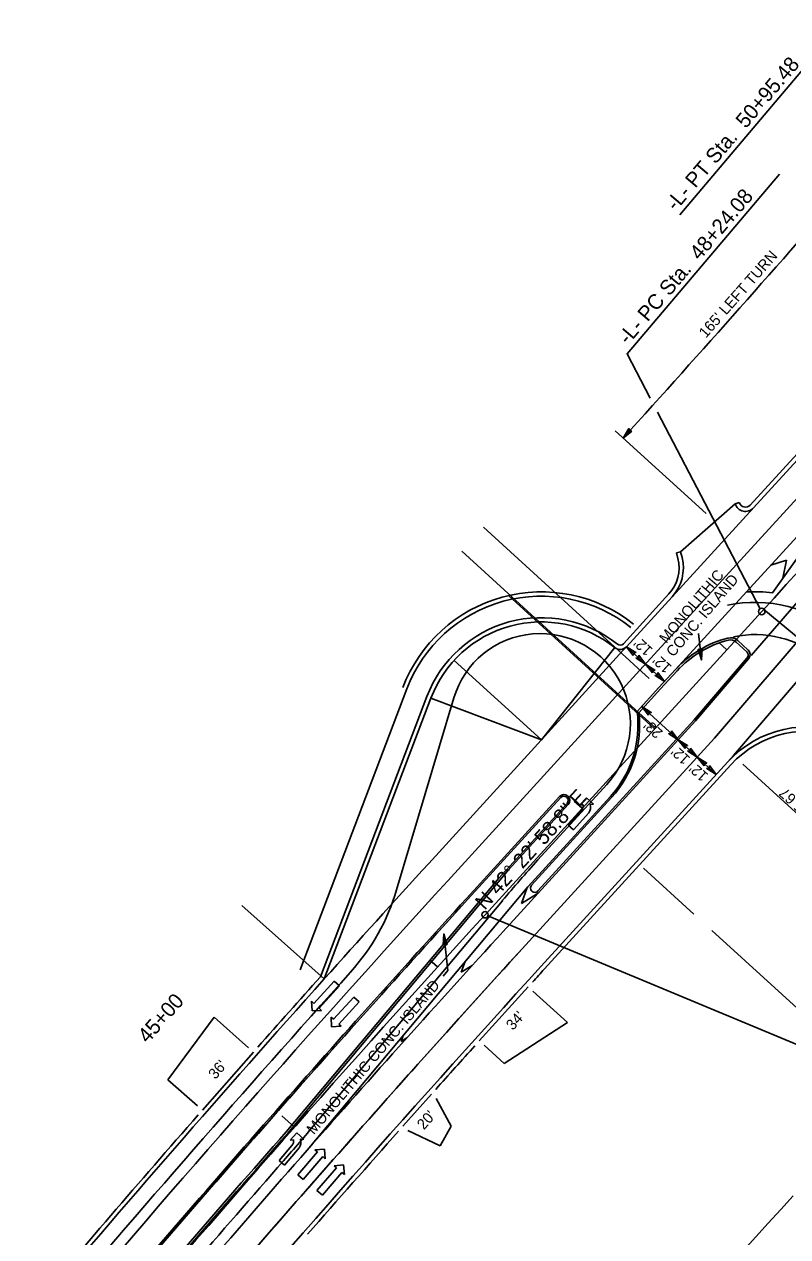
# Model space of a CAD drawing. Extents: x 1761082 to 1764358, y 421907 to 425434.
# Drawn here: x 1763432 to 1763787, y 424529 to 425094 of the extents above; entities that cross this region are included whole.
import ezdxf

# ---------------------------------------------------------------- set-up
doc = ezdxf.new("R2010")
doc.units = 0
for name, color, linetype in [('MARK DUAL LEFT TURN ARROWS CELL', 7, 'Continuous'), ('MARK HOOKS CENTER LEFT TURN ARROW CELL', 7, 'Continuous'), ('MARK HOOKS CENTER STRAIGHT LEFT TURN ARROW CELL', 7, 'Continuous'), ('MARK HOOKS STRAIGHT RIGHT TURN ARROW CELL', 7, 'Continuous'), ('MARK LEFT TURN ARROW CELL', 7, 'Continuous'), ('MARK ONLY WORD SYMBOL CELL', 7, 'Continuous'), ('MARK STRAIGHT RIGHT ARROW CELL', 7, 'Continuous'), ('MARK UTURN ARROW CELL', 7, 'Continuous'), ('Prop Conc Driveway', 7, 'Continuous'), ('Prop Horizontal Alignment Tick Large', 7, 'Continuous'), ('Prop Mkg 3ft Min Skp 3ft Wide White', 7, 'Continuous'), ('Prop Mkg Skp Wht', 7, 'Continuous'), ('Prop Mkg Solid White Diagonals', 7, 'Continuous'), ('Prop Mkg Solid White Edge Line', 7, 'Continuous'), ('Prop Mkg Solid White Lane Line', 7, 'Continuous'), ('Prop Mkg Solid White Multiple Diagonals V8i', 7, 'Continuous'), ('Prop Mkg Solid Yel Skip LT', 7, 'Continuous'), ('Prop Mkg Solid Yel Skip RT', 7, 'Continuous'), ('Prop Mkg Solid Yellow Diagonals', 7, 'Continuous'), ('Prop Mkg Solid Yellow Edge Line', 7, 'Continuous'), ('Prop Mkg Solid Yellow Lane Line', 7, 'Continuous'), ('Prop Mkr CR 80ft Spc', 7, 'Continuous'), ('Scratch_Level_0', 7, 'Continuous'), ('Scratch_Level_1', 7, 'Continuous'), ('Scratch_Level_5', 7, 'Continuous')]:
    doc.layers.add(name, color=color, linetype=linetype)

msp = doc.modelspace()

# ---------------------------------------------------------------- linework, layer by layer
at = {"layer": 'MARK DUAL LEFT TURN ARROWS CELL'}
for p, q in [((1763657.13, 424827.44), (1763725.22, 424765.29)), ((1763609.86, 424783.96), (1763560.14, 424653.11))]:
    msp.add_line(p, q, dxfattribs=at)
for radius in [69, 67]:
    msp.add_arc((1763672.49, 424760.17), radius, 51.5045, 159.1982, dxfattribs=at)
at = {"layer": 'MARK HOOKS CENTER STRAIGHT LEFT TURN ARROW CELL'}
for p, q in [((1763758.93, 424802.23), (1763755.24, 424805.6)), ((1763691.52, 424728.36), (1763687.83, 424731.73)), ((1763624.16, 424654.45), (1763620.46, 424657.8))]:
    msp.add_line(p, q, dxfattribs=at)
at = {"layer": 'MARK LEFT TURN ARROW CELL'}
for p, q in [((1763769.8, 424869.63), (1763835.19, 424941.15)), ((1763764.72, 424870.75), (1763762.82, 424870.15)), ((1763735.45, 424847.4), (1763737.39, 424847.88)), ((1763736.12, 424844.68), (1763735.45, 424847.4)), ((1763710.69, 424804.99), (1763731.93, 424828.22)), ((1763619.2, 424780.41), (1763569.62, 424649.9)), ((1763673.95, 424653.48), (1763760.81, 424748.66))]:
    msp.add_line(p, q, dxfattribs=at)
for centre, radius, start, end in [((1763767.58, 424871.66), 3, 197.5515, 317.5614), ((1763718.64, 424840.36), 18, 317.5614, 13.8599), ((1763672.49, 424760.17), 57, 51.5045, 159.1982), ((1763709.22, 424806.34), 2, 231.5008, 317.5614), ((1763796.27, 424716.3), 48, 67.2642, 137.617), ((1769289.17, 419529.14), 7601.94, 137.617012, 137.679215), ((1769289.17, 419529.14), 7676.94, 138.161609, 138.489892), ((1769289.17, 419529.14), 7601.94, 137.980695, 138.186669), ((1769289.17, 419529.14), 7676.94, 138.803366, 139.730103), ((1769289.17, 419529.14), 7601.94, 138.382631, 138.8659)]:
    msp.add_arc(centre, radius, start, end, dxfattribs=at)
at = {"layer": 'MARK ONLY WORD SYMBOL CELL'}
for p, q in [((1763666.38, 424645.15), (1763643.55, 424619.96)), ((1763514.61, 424587.77), (1763538.39, 424614.79)), ((1763621.29, 424595.16), (1763607.98, 424580.23))]:
    msp.add_line(p, q, dxfattribs=at)
at = {"layer": 'MARK STRAIGHT RIGHT ARROW CELL'}
msp.add_line((1763646.25, 424678.76), (1763775.16, 424820.01), dxfattribs=at)
for centre, start, end in [((1758132.25, 429969.63), 317.617012, 319.652488), ((1769289.17, 419529.14), 137.617012, 139.730103)]:
    msp.add_arc(centre, 7639.44, start, end, dxfattribs=at)
at = {"layer": 'MARK UTURN ARROW CELL'}
for points in [[(1763953.16, 425024.35), (1763812.18, 425093.6), (1763737.01, 425004.87)], [(1763723.17, 424919.43), (1763712.4, 424940.01), (1763783.41, 425023.83)], [(1763774.47, 424821.34), (1763726.57, 424912.93)], [(1763647.64, 424678.18), (1763914.92, 424566.85), (1763986.41, 424651.23)]]:
    msp.add_lwpolyline(points, dxfattribs=at)
for centre in [(1763775.16, 424820.01), (1763646.25, 424678.76)]:
    msp.add_circle(centre, 1.5, dxfattribs=at)
at = {"layer": 'Prop Conc Driveway'}
for p, q in [((1763684.72, 424628.48), (1763668.6, 424643.14)), ((1763498.47, 424601.92), (1763520.06, 424631)), ((1763520.06, 424631), (1763536.14, 424616.78)), ((1763655.12, 424609.51), (1763684.72, 424628.48)), ((1763645.78, 424617.94), (1763655.12, 424609.51)), ((1763512.36, 424589.75), (1763498.47, 424601.92)), ((1763623.53, 424593.16), (1763630.55, 424580.28)), ((1763610.22, 424578.23), (1763625.35, 424571.1)), ((1763625.35, 424571.1), (1763630.55, 424580.28))]:
    msp.add_line(p, q, dxfattribs=at)
at = {"layer": 'Prop Horizontal Alignment Tick Large'}
msp.add_line((1763557.56, 424579.85), (1763551.56, 424585.14), dxfattribs=at)
at = {"layer": 'Prop Mkg 3ft Min Skp 3ft Wide White'}
msp.add_line((1763646.25, 424678.76), (1763775.16, 424820.01), dxfattribs=at)
for centre, start, end in [((1758132.25, 429969.63), 317.617012, 319.652488), ((1769289.17, 419529.14), 137.617012, 139.730103)]:
    msp.add_arc(centre, 7639.44, start, end, dxfattribs=at)
at = {"layer": 'Prop Mkg Skp Wht'}
for p, q in [((1763771.27, 424868.28), (1763836.67, 424939.8)), ((1763737.39, 424847.88), (1763762.82, 424870.15)), ((1763738.06, 424845.16), (1763737.39, 424847.88)), ((1763712.17, 424803.64), (1763733.4, 424826.87)), ((1763621.07, 424779.7), (1763571.36, 424648.84)), ((1763672.48, 424654.83), (1763759.34, 424750.01))]:
    msp.add_line(p, q, dxfattribs=at)
for centre, radius, start, end in [((1763767.58, 424871.66), 5, 197.5515, 317.5614), ((1763718.64, 424840.36), 20, 317.5614, 13.8599), ((1763672.49, 424760.17), 55, 51.5008, 159.1982), ((1763709.22, 424806.34), 4, 231.5008, 317.5614), ((1763796.27, 424716.3), 50, 67.2642, 137.617), ((1769289.17, 419529.14), 7603.94, 137.617012, 139.730103), ((1769289.17, 419529.14), 7674.94, 138.158837, 139.730103)]:
    msp.add_arc(centre, radius, start, end, dxfattribs=at)
at = {"layer": 'Prop Mkg Solid White Diagonals'}
for p, q in [((1763768.27, 424801.25), (1763763.3, 424805.79)), ((1763743.72, 424769.61), (1763768.44, 424798.47)), ((1763735.7, 424792.33), (1763728.03, 424783.94)), ((1763728.03, 424783.94), (1763717.92, 424772.86)), ((1763670.92, 424689.84), (1763743.72, 424769.61)), ((1763681.5, 424733.33), (1763638.31, 424686)), ((1763652.63, 424695.76), (1763684.46, 424730.63)), ((1763705.19, 424733.33), (1763667.97, 424692.54)), ((1763553.57, 424577.59), (1763652.63, 424695.76))]:
    msp.add_line(p, q, dxfattribs=at)
for centre, radius, start, end in [((1763771.86, 424759.26), 49, 104.4881, 137.5628), ((1763760.6, 424802.83), 4, 47.617, 104.4881), ((1763766.92, 424799.77), 2, 319.4164, 47.617), ((1763668.26, 424767.03), 50, 317.617, 6.6974), ((1763682.98, 424731.98), 2, 317.617, 137.617), ((1763669.45, 424691.19), 2, 137.617, 317.617), ((1769289.17, 419529.14), 7650.19, 137.617012, 139.730103), ((1769289.17, 419529.14), 7640.94, 138.645864, 139.730103)]:
    msp.add_arc(centre, radius, start, end, dxfattribs=at)
at = {"layer": 'Prop Mkg Solid White Edge Line'}
for p, q in [((1763645.49, 424859.26), (1763722.71, 424788.79)), ((1763635.38, 424848.18), (1763717.92, 424772.86)), ((1763672.49, 424760.17), (1763631.86, 424797.24)), ((1763663.61, 424662.91), (1763753.14, 424761.02)), ((1763533.04, 424683.09), (1763571.37, 424648.86))]:
    msp.add_line(p, q, dxfattribs=at)
msp.add_arc((1769289.17, 419529.14), 7615.94, 137.617012, 139.730103, dxfattribs=at)
at = {"layer": 'Prop Mkg Solid White Lane Line'}
for p, q in [((1763768.27, 424801.25), (1763763.3, 424805.79)), ((1763743.72, 424769.61), (1763768.44, 424798.47)), ((1763728.03, 424783.94), (1763735.7, 424792.33)), ((1763717.92, 424772.86), (1763728.03, 424783.94)), ((1763670.92, 424689.84), (1763743.72, 424769.61)), ((1763638.31, 424686), (1763681.5, 424733.33)), ((1763652.63, 424695.76), (1763684.46, 424730.63)), ((1763667.97, 424692.54), (1763705.19, 424733.33)), ((1763652.63, 424695.76), (1763553.57, 424577.59))]:
    msp.add_line(p, q, dxfattribs=at)
for centre, radius, start, end in [((1763771.86, 424759.26), 49, 104.4881, 137.5628), ((1763760.6, 424802.83), 4, 47.617, 104.4881), ((1763766.92, 424799.77), 2, 319.4164, 47.617), ((1763668.26, 424767.03), 50, 317.617, 6.6974), ((1763682.98, 424731.98), 2, 317.617, 137.617), ((1763669.45, 424691.19), 2, 137.617, 317.617), ((1769289.17, 419529.14), 7650.19, 137.617012, 138.645864), ((1769289.17, 419529.14), 7650.19, 138.645864, 139.730103), ((1769289.17, 419529.14), 7640.94, 138.645864, 139.730103)]:
    msp.add_arc(centre, radius, start, end, dxfattribs=at)
at = {"layer": 'Prop Mkg Solid White Multiple Diagonals V8i'}
for p, q in [((1763734.96, 424793), (1763768.01, 424829.16)), ((1763672.49, 424760.17), (1763706.73, 424803.21)), ((1763672.49, 424760.17), (1763621.07, 424779.7))]:
    msp.add_line(p, q, dxfattribs=at)
for radius in [65, 50]:
    msp.add_arc((1763771.86, 424759.26), radius, 51.059, 101.278, dxfattribs=at)
at = {"layer": 'Prop Mkg Solid Yel Skip RT'}
for p, q in [((1763749.27, 424865.73), (1763706.88, 424904.25)), ((1763712.17, 424803.64), (1763729.9, 424787.46)), ((1763719.26, 424775.82), (1763753.98, 424744.14)), ((1763766.37, 424748.95), (1763797.92, 424720.16)), ((1763720.07, 424700.5), (1763743.52, 424679.1)), ((1763751.92, 424671.43), (1763823.83, 424605.81))]:
    msp.add_line(p, q, dxfattribs=at)
for points in [[(1763745.65, 424809.82), (1763747.08, 424797.45)], [(1763627.04, 424669.8), (1763629, 424652.81), (1763626.73, 424650.13)]]:
    msp.add_lwpolyline(points, dxfattribs=at)
for centre, radius, start, end in [((1758076.76, 430009.28), 7605.02, 317.799981, 319.027687), ((1769289.17, 419529.14), 7445.13, 137.617012, 139.730103)]:
    msp.add_arc(centre, radius, start, end, dxfattribs=at)
at = {"layer": 'Prop Mkg Solid Yellow Diagonals'}
for p, q in [((1763693.53, 424733.21), (1763690.49, 424729.89)), ((1763696.78, 424730.23), (1763693.53, 424733.21)), ((1763695.29, 424730.15), (1763696.78, 424730.23)), ((1763691.16, 424727.35), (1763685.05, 424720.53)), ((1763687.51, 424718.33), (1763694.55, 424726.18)), ((1763690.49, 424729.89), (1763691.97, 424729.97)), ((1763685.05, 424720.53), (1763687.51, 424718.33)), ((1763566.53, 424637.45), (1763575.97, 424647.79)), ((1763578.4, 424645.56), (1763568.96, 424635.22)), ((1763575.97, 424647.79), (1763578.4, 424645.56)), ((1763575.68, 424630.06), (1763585.11, 424640.4)), ((1763585.11, 424640.4), (1763587.55, 424638.18)), ((1763565.66, 424633.97), (1763565.42, 424638.46)), ((1763565.42, 424638.46), (1763566.53, 424637.45)), ((1763570.07, 424634.21), (1763565.66, 424633.97)), ((1763568.96, 424635.22), (1763570.07, 424634.21)), ((1763587.55, 424638.18), (1763578.11, 424627.84)), ((1763574.81, 424626.59), (1763574.57, 424631.07)), ((1763574.57, 424631.07), (1763575.68, 424630.06)), ((1763579.22, 424626.82), (1763574.81, 424626.59)), ((1763578.11, 424627.84), (1763579.22, 424626.82)), ((1763558.51, 424577.14), (1763555.55, 424573.76)), ((1763555.55, 424573.76), (1763557.03, 424573.87)), ((1763561.82, 424574.24), (1763558.51, 424577.14)), ((1763560.34, 424574.13), (1763561.82, 424574.24)), ((1763556.28, 424571.23), (1763550.32, 424564.28)), ((1763552.83, 424562.13), (1763559.69, 424570.14)), ((1763559.04, 424557.62), (1763568.16, 424568.24)), ((1763567.02, 424569.21), (1763571.43, 424569.58)), ((1763568.16, 424568.24), (1763567.02, 424569.21)), ((1763571.43, 424569.58), (1763571.8, 424565.11)), ((1763550.32, 424564.28), (1763552.83, 424562.13)), ((1763570.66, 424566.09), (1763561.54, 424555.47)), ((1763567.96, 424550.24), (1763577.09, 424560.86)), ((1763571.8, 424565.11), (1763570.66, 424566.09)), ((1763575.95, 424561.84), (1763580.35, 424562.2)), ((1763577.09, 424560.86), (1763575.95, 424561.84)), ((1763580.35, 424562.2), (1763580.73, 424557.73)), ((1763561.54, 424555.47), (1763559.04, 424557.62)), ((1763579.59, 424558.71), (1763570.47, 424548.09)), ((1763580.73, 424557.73), (1763579.59, 424558.71)), ((1763570.47, 424548.09), (1763567.96, 424550.24))]:
    msp.add_line(p, q, dxfattribs=at)
for centre, radius, start, end in [((1763688.74, 424729.53), 3.27, 318.1057, 7.7639), ((1763690.17, 424729.05), 5.25, 326.7817, 12.0934), ((1763553.81, 424573.35), 3.27, 319.4106, 9.0688), ((1763555.25, 424572.91), 5.25, 328.0867, 13.3984)]:
    msp.add_arc(centre, radius, start, end, dxfattribs=at)
at = {"layer": 'Prop Mkg Solid Yellow Edge Line'}
for p, q in [((1763718.44, 424792.72), (1763947.38, 425043.11)), ((1763753.14, 424761.02), (1763974.82, 425019.8)), ((1763733.4, 424826.87), (1763771.27, 424868.28)), ((1763762.01, 424752.93), (1763857.92, 424865.11)), ((1763770.31, 424799.5), (1763793, 424825.99)), ((1763620.03, 424702.69), (1763712.17, 424803.65)), ((1763628.89, 424694.6), (1763718.43, 424792.7)), ((1763663.61, 424662.91), (1763753.14, 424761.02)), ((1763759.34, 424750.01), (1763762.01, 424752.93))]:
    msp.add_line(p, q, dxfattribs=at)
for radius, start, end in [(7674.94, 137.617012, 138.158837), (7662.94, 137.617012, 139.730103), (7615.94, 137.617012, 138.644778), (7627.94, 138.644778, 139.730103), (7615.94, 138.644778, 139.730103)]:
    msp.add_arc((1769289.17, 419529.14), radius, start, end, dxfattribs=at)
at = {"layer": 'Prop Mkg Solid Yellow Lane Line'}
for points in [[(1763714.64, 424904.06), (1763710.59, 424900.83), (1763713.32, 424905.27), (1763713.56, 424904.18)], [(1763715.34, 424799.55), (1763712.17, 424803.64), (1763716.57, 424800.85), (1763715.48, 424800.62)], [(1763717.85, 424799.64), (1763721.03, 424795.55), (1763716.63, 424798.34), (1763717.72, 424798.57)], [(1763747.37, 424802.62), (1763747.08, 424797.45), (1763745.59, 424802.44), (1763746.57, 424801.9)], [(1763724.21, 424791.46), (1763721.03, 424795.55), (1763725.43, 424792.76), (1763724.34, 424792.53)], [(1763726.72, 424791.55), (1763729.9, 424787.46), (1763725.49, 424790.25), (1763726.59, 424790.48)], [(1763722.44, 424771.73), (1763719.26, 424775.82), (1763723.66, 424773.03), (1763722.57, 424772.8)], [(1763733.07, 424764.4), (1763736.25, 424760.31), (1763731.85, 424763.1), (1763732.94, 424763.33)], [(1763739.43, 424756.23), (1763736.25, 424760.31), (1763740.65, 424757.53), (1763739.56, 424757.3)], [(1763741.94, 424756.31), (1763745.12, 424752.23), (1763740.71, 424755.01), (1763741.81, 424755.25)], [(1763748.29, 424748.14), (1763745.12, 424752.23), (1763749.52, 424749.44), (1763748.42, 424749.21)], [(1763750.8, 424748.23), (1763753.98, 424744.14), (1763749.58, 424746.93), (1763750.67, 424747.16)], [(1763626.75, 424664.63), (1763627.04, 424669.8), (1763628.53, 424664.81), (1763627.55, 424665.35)]]:
    msp.add_lwpolyline(points, close=True, dxfattribs=at)
at = {"layer": 'Prop Mkr CR 80ft Spc'}
msp.add_line((1763776.07, 424821.01), (1763909.73, 424710.27), dxfattribs=at)
at = {"layer": 'Scratch_Level_0'}
for p, q in [((1763768.01, 424829.16), (1763823.69, 424890.05)), ((1763780.25, 424828.76), (1763823.69, 424890.05)), ((1763786.65, 424843.96), (1763779.36, 424841.56)), ((1763786.65, 424843.96), (1763785.06, 424835.53)), ((1763768.76, 424802.16), (1763763.97, 424806.52)), ((1763744.28, 424769.11), (1763769.01, 424797.99)), ((1763727.29, 424784.62), (1763734.96, 424793)), ((1763717.09, 424773.44), (1763727.29, 424784.62)), ((1763654.75, 424671), (1763744.28, 424769.11)), ((1763637.76, 424686.51), (1763680.95, 424733.83)), ((1763666.24, 424691.75), (1763704.64, 424733.83)), ((1763657.2, 424699.66), (1763685.01, 424730.13)), ((1763554.32, 424576.93), (1763657.2, 424699.66)), ((1763563.42, 424569.11), (1763666.24, 424691.75)), ((1763665.93, 424691.39), (1763663.19, 424684.06)), ((1763663.19, 424684.06), (1763670.99, 424688.81)), ((1763637.05, 424656.93), (1763635.2, 424651.99)), ((1763635.2, 424651.99), (1763640.22, 424655.04)), ((1763608.16, 424622.48), (1763607.13, 424619.71)), ((1763607.13, 424619.71), (1763609.84, 424621.35)), ((1763579.28, 424588.02), (1763578.93, 424587.09)), ((1763578.93, 424587.09), (1763579.73, 424587.57))]:
    msp.add_line(p, q, dxfattribs=at)
for centre, radius, start, end in [((1763771.86, 424759.26), 70, 83.1106, 93.1475), ((1763771.86, 424759.26), 50, 104.4881, 137.5628), ((1763760.6, 424802.83), 5, 47.617, 104.4881), ((1763766.74, 424799.94), 3, 319.4164, 47.617), ((1763668.26, 424767.03), 49.25, 317.617, 7.4761), ((1763682.98, 424731.98), 2.75, 317.617, 137.617), ((1769289.17, 419529.14), 7650.94, 137.617012, 138.645864), ((1769289.17, 419529.14), 7627.94, 137.617012, 138.644778), ((1769289.17, 419529.14), 7650.94, 138.645864, 139.730103), ((1769289.17, 419529.14), 7639.94, 138.645864, 139.730103)]:
    msp.add_arc(centre, radius, start, end, dxfattribs=at)
at = {"layer": 'Scratch_Level_1'}
for p, q in [((1763631.7, 424779.73), (1763605.07, 424690.32)), ((1763702.98, 424739.43), (1763670.89, 424704.27)), ((1763567.14, 424581.32), (1763654.32, 424685.31))]:
    msp.add_line(p, q, dxfattribs=at)
for centre in [(1763631.7, 424779.73), (1763631.7, 424779.73), (1763631.7, 424779.73), (1763631.7, 424779.73), (1763631.7, 424779.73), (1763631.7, 424779.73), (1763702.98, 424739.43), (1763702.98, 424739.43), (1763702.98, 424739.43), (1763702.98, 424739.43), (1763702.98, 424739.43), (1763702.98, 424739.43), (1763670.89, 424704.27), (1763670.89, 424704.27), (1763670.89, 424704.27), (1763670.89, 424704.27), (1763670.89, 424704.27), (1763670.89, 424704.27), (1763605.07, 424690.32), (1763605.07, 424690.32), (1763605.07, 424690.32), (1763605.07, 424690.32), (1763605.07, 424690.32), (1763605.07, 424690.32), (1763654.32, 424685.31), (1763654.32, 424685.31), (1763654.32, 424685.31), (1763654.32, 424685.31), (1763654.32, 424685.31), (1763654.32, 424685.31), (1763583.64, 424652.05), (1763583.64, 424652.05), (1763583.64, 424652.05), (1763583.64, 424652.05), (1763583.64, 424652.05), (1763583.64, 424652.05), (1763567.14, 424581.32), (1763567.14, 424581.32), (1763567.14, 424581.32), (1763567.14, 424581.32), (1763567.14, 424581.32), (1763567.14, 424581.32), (1763552.38, 424564.12), (1763552.38, 424564.12), (1763552.38, 424564.12), (1763552.38, 424564.12), (1763552.38, 424564.12), (1763552.38, 424564.12)]:
    msp.add_circle(centre, 0.0417, dxfattribs=at)
for centre, radius, start, end in [((1763671.95, 424767.74), 42, 317.6215, 163.4155), ((1764114.12, 424299.85), 600, 137.62146, 140.02618), ((1763509.23, 424718.86), 100, 318.0798, 343.4155), ((1769289.17, 419529.14), 7667.94, 138.0798, 139.730103), ((1762800.8, 425223.76), 1000, 318.72768, 320.02618), ((1769289.17, 419529.14), 7632.94, 138.727677, 139.730103)]:
    msp.add_arc(centre, radius, start, end, dxfattribs=at)
at = {"layer": 'Scratch_Level_5'}
msp.add_line((1763717.92, 424772.86), (1763725.67, 424765.78), dxfattribs=at)

# ---------------------------------------------------------------- texts
at = {"layer": 'MARK HOOKS CENTER LEFT TURN ARROW CELL'}
msp.add_text('N 42%%d 22\' 58.8" E', height=7, rotation=47.617, dxfattribs=at).set_placement((1763646.15, 424680.52))
at = {"layer": 'MARK HOOKS STRAIGHT RIGHT TURN ARROW CELL'}
msp.add_text('45+00', height=7, rotation=48.6134, dxfattribs=at).set_placement((1763489.08, 424618.47))
at = {"layer": 'MARK UTURN ARROW CELL'}
for s, p in [('-L- PT Sta.  50+95.48', (1763735.14, 425006.21)), ('-L- PC Sta.  48+24.08', (1763712.94, 424943.94))]:
    msp.add_text(s, height=7, rotation=49.7301, dxfattribs=at).set_placement(p)
at = {"layer": 'Prop Mkg Solid Yel Skip LT'}
for s, rotation, p in [("165' LEFT TURN", 48.6656, (1763749.14, 424947.12)), ('MONOLITHIC', 49.7301, (1763730.74, 424804.83)), ('CONC. ISLAND', 49.7301, (1763733.96, 424798.5)), ("12'", 137.617, (1763724.75, 424802.46)), ("12'", 137.617, (1763733.61, 424794.38)), ("23'", 137.617, (1763729.39, 424764.08)), ("12'", 137.617, (1763742.18, 424751.83)), ("12'", 137.617, (1763750.59, 424743.96)), ('+65.67', 137.617, (1763801.38, 424724.49)), ('MONOLITHIC CONC. ISLAND', 49.7301, (1763566.47, 424576.04)), ("34'", 47.623, (1763659.23, 424624.61)), ("36'", 49.5276, (1763520.67, 424601.75)), ("20'", 48.3712, (1763617.77, 424578.26))]:
    msp.add_text(s, height=5, rotation=rotation, dxfattribs=at).set_placement(p)

doc.saveas('drawing.dxf')
